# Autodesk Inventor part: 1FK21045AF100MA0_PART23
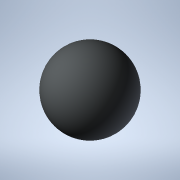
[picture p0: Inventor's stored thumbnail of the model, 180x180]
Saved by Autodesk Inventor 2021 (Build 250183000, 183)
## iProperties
Created: 2025-04
Part Number: 1FK21045AF100MA0_PART23
Material: Generic
Catalog Web Link: www.3dfindit.com
Description: -Servo synchronous motor
Document SubType Name: Modeling
Designer: psAdmin
Mass: 0.137258 g
Surface Area: 1.2868 cm^2
Volume: 0.137258 cm^3
Density: 1 g/cm^3
Appearance: PSOLRGB-212-217-219
Category: PARTsolutions
Title: 1FK21045AF100MA0_PART23
Author: Cadenas PARTsolutions
Comments: Servo synchronous motor
Sending System: PARTsolutions
Preprocessor: ST-DEVELOPER v19.3
PSOL_IDENT_0: {$CADENAS_DATA/23d-libs/siemens_ag/_cat_/52/6b/1fk21045af100ma0.prj},216 {VTYP=3D},{NB=1FK21045AF100
PSOL_IDENT_1: MA0_PART23},{LINA=1FK21045AF100MA0_PART23},{NN=1FK21045AF100MA0_PART23},{NOPRJ=TRUE},{DATE=19.08.202
PSOL_IDENT_2: 5 14:00:38},{GEOMDATE=30.07.2025 02:01:45},{VERSION=},{LINEID=10},{WBVAR=},{WBNUMERIC=}  {NB=1FK2104
PSOL_IDENT_3: 5AF100MA0_PART23},{LINA=1FK21045AF100MA0_PART23},{KT=DUMMY},{PREVIEW=../../../_pool_/cb/72/p_d211_xx
PSOL_IDENT_4: _00434j.png},{DESCSHORT=SIMOTICS S-1FK2 HD, SINAMICS S210 3AC 400V-480V, 2.4 Nm, 3000 rpm},{DESCLONG=
PSOL_IDENT_5: SIMOTICS S-1FK2 HD servo motor M0=2.4 Nm; PN = 0.75 kW at nN=3000 rpm (380-480 V); PN = 0.375 kW at
PSOL_IDENT_6: nN=1500 rpm (200-240 V); with holding brake; degree of protection IP64; cylindrical shaft D19x40mm;
PSOL_IDENT_7: absolute encoder 22-bit + 12-bit multiturn (encoder AM22DQC); with OCC interface; plug size M17, rot
PSOL_IDENT_8: atable; SIMOTICS S-1FK2 servomotorfor a wide range of uses in industrial environments. SIMOTICS S‑1F
PSOL_IDENT_9: K2 servomotors are compact synchronous motors with a high dynamic performance that set themselves ap
PSOL_IDENT_10: art as a result of their high power density, degree of protection and overload capability. The motor
PSOL_IDENT_11: s are available in two variants: as High Dynamic variant (highest dynamic performance as a result of
PSOL_IDENT_12: the low intrinsic moment of inertia for applications demanding a high dynamic performance with low
PSOL_IDENT_13: moved masses) - and as Compact variant (precise and stable closed-loop control for medium up to larg
PSOL_IDENT_14: e moved masses as a result of a medium intrinsic moment of inertia). SIMOTICSS‑1FK2 servomotors full
PSOL_IDENT_15: y exploit their strengths in a system with the SINAMICSS210 frequency converter and simple connectio
PSOL_IDENT_16: n using the one cable connection (OCC). Advantages include the short control and positioning times,
PSOL_IDENT_17: fast and precise correction of disturbing quantities as well as stable control with a high dynamic p
PSOL_IDENT_18: erformance. The servo motors can be configured to address a wide range of requirements. For example
PSOL_IDENT_19: with and without holding brake, IP64 or IP65 degree of protection, singleturn or multiturn absolute
PSOL_IDENT_20: encoders - to name just a few. Further, the servomotors are available in different shaft heights ext
PSOL_IDENT_21: ending from 20 to 100. A shaft sealing ring is available to achieve an IP65 degree of protection and
PSOL_IDENT_22: for subsequent mounting at the motor or as spare part. SIMOTICS - the optimum motor for each and ev
PSOL_IDENT_23: ery motion control application.},{INTNO=804766906411},{SUPPLIERALTNO=1FK2104-5AF10-0MA0},{MANUID=1FK
PSOL_IDENT_24: 21045AF100MA0},{MANUNAME=Siemens},{MANUTYPEDESC=Synchronous motor 1FK2-HD 2.4 NM},{AAU732=SIMOTICS},
PSOL_IDENT_25: {AAO057=S-1FK2},{AAU734=SIMOTICS S-1FK2 HD servo motor M0=2.4 Nm; PN = 0.75 kW at nN=3000 rpm (380-4
PSOL_IDENT_26: 80 V); PN = 0.375 kW at nN=1500 rpm (200-240 V); with holding brake; degree of protection IP64; cyli
PSOL_IDENT_27: ndrical shaft D19x40mm; absolute encoder 22-bit + 12-bit multiturn (encoder AM22DQC); with OCC inter
PSOL_IDENT_28: face; plug size M17, rotatable;},{AAW338=Synchronous motor 1FK2-HD 2.4 NM},{AAO742=SIMOTICS},{AAO663=
PSOL_IDENT_29: 4042948693070},{NOCUPEROU=1},{PRICEQUANTITY=1},{QUANTITYMIN=1},{QUANTITYINT=1},{CTN=85015100},{COO=D
PSOL_IDENT_30: E},{AAO676=1FK2104-5AF10-0MA0},{AAO677=Siemens AG},{ORDERUNIT=C62},{CONTENTUNIT=C62}
NB: 1FK21045AF100MA0_PART23
NT: Servo synchronous motor
NBSYN: $MANUID._PART23
LINA: 1FK21045AF100MA0_PART23
CATALOG: SIEMENS
PREVIEW: ../../../_pool_/cb/72/p_d211_xx_00434j.png
DESCSHORT: SIMOTICS S-1FK2 HD, SINAMICS S210 3AC 400V-480V, 2.4 Nm, 3000 rpm
DESCLONG: SIMOTICS S-1FK2 HD servo motor M0=2.4 Nm; PN = 0.75 kW at nN=3000 rpm (380-480 V); PN = 0.375 kW at nN=1500 rpm (200-240 V); with holding brake; degree of prote
INTNO: 804766906411
SUPPLIERALTNO: 1FK2104-5AF10-0MA0
MANUID: 1FK21045AF100MA0
MANUNAME: Siemens
MANUTYPEDESC: Synchronous motor 1FK2-HD 2.4 NM
AAU732: SIMOTICS
AAO057: S-1FK2
AAU734: SIMOTICS S-1FK2 HD servo motor M0=2.4 Nm; PN = 0.75 kW at nN=3000 rpm (380-480 V); PN = 0.375 kW at nN=1500 rpm (200-240 V); with holding brake; degree of prote
AAW338: Synchronous motor 1FK2-HD 2.4 NM
AAO742: SIMOTICS
AAO663: 4042948693070.0
NOCUPEROU: 1
PRICEQUANTITY: 1
QUANTITYMIN: 1
QUANTITYINT: 1
CTN: 85015100
COO: DE
ARTICLENO: 1FK21045AF100MA0_PART23
BOMINFO: 1FK21045AF100MA0_PART23
CREATOR: CADENAS GmbH
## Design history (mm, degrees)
feature "2025_04_17_15_34_52_0317"
body "Solid1"
